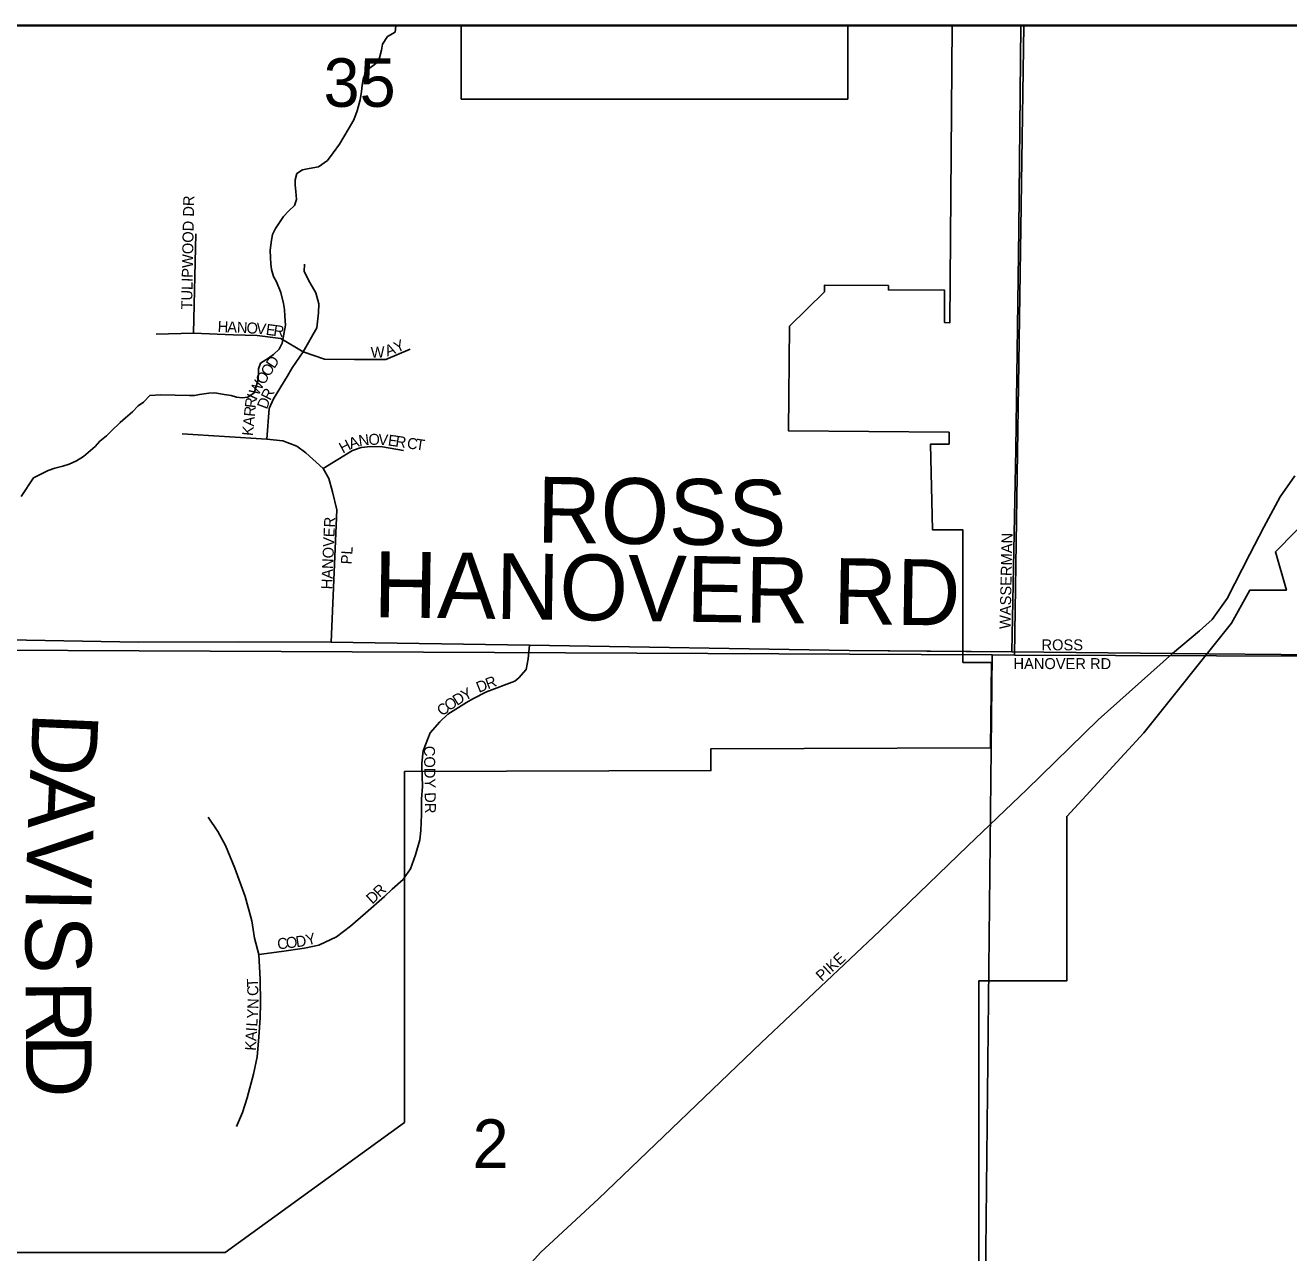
# Model space of a CAD drawing. Extents: x 0 to 34, y -2.3 to 22.
# Drawn here: x 6.815 to 7.907, y 19.84 to 20.9 of the extents above; entities that cross this region are included whole.
import ezdxf

# ---------------------------------------------------------------- set-up
doc = ezdxf.new("R2010")
doc.units = 0
for name, color, linetype in [('GM_X_City_Street', 7, 'Continuous'), ('GM_X_City_Street_Text', 7, 'Continuous'), ('GM_X_Corporation', 7, 'Continuous'), ('GM_X_County', 7, 'Continuous'), ('GM_X_County_Road', 7, 'Continuous'), ('GM_X_County_Road_Text', 7, 'Continuous'), ('GM_X_Minor_River', 7, 'Continuous'), ('GM_X_Section', 7, 'Continuous'), ('GM_X_Section_Text', 7, 'Continuous'), ('GM_X_Township', 7, 'Continuous'), ('GM_X_Township_Road_Text', 7, 'Continuous'), ('GM_X_Township_Subdivision', 7, 'Continuous'), ('GM_X_Township_Subdivision_Text', 7, 'Continuous'), ('SH_Data', 7, 'Continuous')]:
    doc.layers.add(name, color=color, linetype=linetype)

msp = doc.modelspace()

# ---------------------------------------------------------------- linework, layer by layer
at = {"layer": 'GM_X_City_Street'}
for p, q in [((7.6735, 20.7239), (7.6753, 20.8994)), ((7.6709, 20.5341), (7.6735, 20.7239)), ((7.6675, 20.359), (7.6709, 20.5341)), ((7.8992, 20.4928), (7.9119, 20.511)), ((7.885, 20.4666), (7.8992, 20.4928)), ((7.8729, 20.4434), (7.885, 20.4666)), ((7.8533, 20.4052), (7.8729, 20.4434)), ((7.8405, 20.387), (7.8533, 20.4052)), ((7.8296, 20.3771), (7.8405, 20.387)), ((7.8061, 20.3576), (7.8296, 20.3771)), ((7.6276, 20.3594), (7.6675, 20.359)), ((7.6675, 20.359), (7.8061, 20.3576)), ((7.7421, 20.3005), (7.8061, 20.3576)), ((7.8061, 20.3576), (7.8061, 20.3576)), ((7.6805, 20.2403), (7.7421, 20.3005)), ((7.1578, 20.2607), (7.158, 20.2631)), ((7.1585, 20.2428), (7.1578, 20.2607)), ((7.1575, 20.2318), (7.1585, 20.2428)), ((7.6295, 20.1916), (7.6805, 20.2403)), ((7.1576, 20.2187), (7.1575, 20.2318)), ((7.157, 20.2049), (7.1576, 20.2187)), ((7.1525, 20.1838), (7.1561, 20.1969)), ((7.1561, 20.1969), (7.157, 20.2049)), ((7.5535, 20.1183), (7.6295, 20.1916)), ((7.148, 20.1717), (7.1525, 20.1838)), ((7.1441, 20.166), (7.148, 20.1717)), ((7.4509, 20.0216), (7.5535, 20.1183)), ((7.3106, 19.887), (7.4509, 20.0216)), ((7.2603, 19.8406), (7.3106, 19.887)), ((7.2401, 19.8181), (7.2603, 19.8406))]:
    msp.add_line(p, q, dxfattribs=at)
at = {"layer": 'GM_X_Corporation'}
for p, q in [((7.5257, 20.8994), (7.1919, 20.8994)), ((7.1919, 20.8994), (7.192, 20.8362)), ((7.5257, 20.8362), (7.5257, 20.8994)), ((7.192, 20.8362), (7.5257, 20.8362))]:
    msp.add_line(p, q, dxfattribs=at)
for points in [[(7.6158, 20.8994), (7.6139, 20.6432), (7.6093, 20.6433), (7.6093, 20.6712), (7.5609, 20.6715), (7.5609, 20.6753), (7.5056, 20.6756), (7.5056, 20.6699), (7.4753, 20.6402), (7.4746, 20.5498), (7.6132, 20.5486), (7.6132, 20.5385), (7.5972, 20.5385), (7.5989, 20.4643), (7.6251, 20.4643), (7.6252, 20.35), (7.6499, 20.35), (7.649, 20.2763), (7.4075, 20.2755), (7.4075, 20.2566), (7.1428, 20.2557), (7.1428, 19.9527), (6.988, 19.8406), (6.6565, 19.8406)], [(8.8792, 19.7101), (8.8792, 20.8994), (7.6158, 20.8994)], [(6.7701, 19.2725), (6.8438, 19.2151), (6.8806, 19.2101), (7.0229, 19.2342), (7.1292, 19.2244), (7.1274, 19.3364), (7.6387, 19.3364), (7.6388, 20.075), (7.7148, 20.075), (7.7148, 20.217), (7.7814, 20.2892), (7.8572, 20.3839), (7.8729, 20.4123), (7.9045, 20.4123), (7.8951, 20.4454), (7.9466, 20.4977)]]:
    msp.add_lwpolyline(points, dxfattribs=at)
at = {"layer": 'GM_X_County'}
msp.add_line((8.8792, 20.8994), (2.0792, 20.8994), dxfattribs=at)
at = {"layer": 'GM_X_County_Road'}
for p, q in [((6.8005, 20.3694), (6.9133, 20.3674)), ((6.9133, 20.3674), (6.9998, 20.3678)), ((6.9998, 20.3678), (7.0796, 20.3674)), ((7.0796, 20.3674), (7.2509, 20.365)), ((7.2509, 20.365), (7.5268, 20.3604)), ((7.5268, 20.3604), (7.6276, 20.3594))]:
    msp.add_line(p, q, dxfattribs=at)
at = {"layer": 'GM_X_Minor_River'}
for p, q in [((7.1348, 20.894), (7.1355, 20.8994)), ((7.1239, 20.8836), (7.1282, 20.8904)), ((7.1282, 20.8904), (7.1348, 20.894)), ((7.1213, 20.872), (7.123, 20.8784)), ((7.123, 20.8784), (7.1239, 20.8836)), ((7.1093, 20.859), (7.1135, 20.8635)), ((7.1135, 20.8635), (7.1178, 20.8668)), ((7.1178, 20.8668), (7.1213, 20.872)), ((7.1063, 20.8481), (7.1072, 20.8534)), ((7.1072, 20.8534), (7.1093, 20.859)), ((7.1045, 20.8357), (7.1058, 20.8428)), ((7.1058, 20.8428), (7.1063, 20.8481)), ((7.102, 20.8262), (7.1045, 20.8357)), ((7.0992, 20.8184), (7.102, 20.8262)), ((7.0869, 20.7975), (7.0944, 20.8101)), ((7.0944, 20.8101), (7.0992, 20.8184)), ((7.0814, 20.79), (7.0869, 20.7975)), ((7.0763, 20.7833), (7.0814, 20.79)), ((7.0498, 20.7719), (7.0549, 20.7752)), ((7.0549, 20.7752), (7.0606, 20.7765)), ((7.0606, 20.7765), (7.0686, 20.7778)), ((7.0686, 20.7778), (7.0763, 20.7833)), ((7.0485, 20.7621), (7.0486, 20.7666)), ((7.0486, 20.7666), (7.0498, 20.7719)), ((7.0491, 20.7564), (7.0485, 20.7621)), ((7.0497, 20.7495), (7.0491, 20.7564)), ((7.043, 20.7399), (7.048, 20.7443)), ((7.048, 20.7443), (7.0497, 20.7495)), ((7.0316, 20.7246), (7.0383, 20.735)), ((7.0383, 20.735), (7.043, 20.7399)), ((7.0288, 20.7194), (7.0316, 20.7246)), ((7.027, 20.7058), (7.028, 20.7145)), ((7.028, 20.7145), (7.0288, 20.7194)), ((7.0272, 20.6993), (7.027, 20.7058)), ((7.0275, 20.694), (7.0272, 20.6993)), ((7.0281, 20.6891), (7.0275, 20.694)), ((7.0299, 20.683), (7.0281, 20.6891)), ((7.0324, 20.6784), (7.0299, 20.683)), ((7.036, 20.6692), (7.0324, 20.6784)), ((7.0384, 20.6597), (7.036, 20.6692)), ((7.0394, 20.6547), (7.0384, 20.6597)), ((7.0397, 20.649), (7.0394, 20.6547)), ((7.0402, 20.641), (7.0397, 20.649)), ((7.0372, 20.6256), (7.0402, 20.641)), ((7.0348, 20.6204), (7.0372, 20.6256)), ((7.0186, 20.6083), (7.0255, 20.6126)), ((7.0255, 20.6126), (7.0298, 20.6159)), ((7.0298, 20.6159), (7.0348, 20.6204)), ((7.0168, 20.5992), (7.0169, 20.6034)), ((7.0169, 20.6034), (7.0186, 20.6083)), ((7.013, 20.5826), (7.0163, 20.5928)), ((7.0163, 20.5928), (7.0168, 20.5992)), ((6.9176, 20.5745), (6.923, 20.5804)), ((6.923, 20.5804), (6.9325, 20.5809)), ((6.9325, 20.5809), (6.9572, 20.5803)), ((6.9572, 20.5803), (6.9617, 20.5805)), ((6.9617, 20.5805), (6.9659, 20.5812)), ((6.9659, 20.5812), (6.9739, 20.5825)), ((6.9739, 20.5825), (6.9792, 20.5827)), ((6.9792, 20.5827), (6.9872, 20.5814)), ((6.9872, 20.5814), (6.9932, 20.5805)), ((6.9932, 20.5805), (6.9978, 20.5789)), ((6.9978, 20.5789), (7.0027, 20.5784)), ((7.0027, 20.5784), (7.0076, 20.579)), ((7.0076, 20.579), (7.013, 20.5826)), ((6.9079, 20.5664), (6.9129, 20.5715)), ((6.9129, 20.5715), (6.9176, 20.5745)), ((6.89, 20.5498), (6.8974, 20.5572)), ((6.8974, 20.5572), (6.9021, 20.5612)), ((6.9021, 20.5612), (6.9079, 20.5664)), ((6.8857, 20.5457), (6.89, 20.5498)), ((6.8656, 20.5277), (6.8757, 20.5365)), ((6.8757, 20.5365), (6.8799, 20.5409)), ((6.8799, 20.5409), (6.8857, 20.5457)), ((6.8533, 20.5212), (6.8598, 20.524)), ((6.8598, 20.524), (6.8656, 20.5277)), ((6.8272, 20.5116), (6.8353, 20.5156)), ((6.8353, 20.5156), (6.841, 20.5177)), ((6.841, 20.5177), (6.8479, 20.5194)), ((6.8479, 20.5194), (6.8533, 20.5212)), ((6.812, 20.4931), (6.8226, 20.5094)), ((6.8226, 20.5094), (6.8272, 20.5116))]:
    msp.add_line(p, q, dxfattribs=at)
at = {"layer": 'GM_X_Section'}
for p, q in [((7.6777, 20.8994), (6.6703, 20.8994)), ((7.6696, 20.3563), (7.6777, 20.8994)), ((7.6777, 20.8994), (7.6696, 20.3563)), ((8.6806, 20.8994), (7.6777, 20.8994)), ((6.6643, 20.361), (7.6503, 20.3564)), ((6.6643, 20.361), (7.6503, 20.3564)), ((7.6503, 20.3564), (7.6398, 19.3493)), ((7.6398, 19.3493), (7.6503, 20.3564)), ((7.6503, 20.3564), (7.6696, 20.3563)), ((7.6503, 20.3564), (7.6696, 20.3563)), ((7.6696, 20.3563), (8.67, 20.3528)), ((7.6696, 20.3563), (8.67, 20.3528))]:
    msp.add_line(p, q, dxfattribs=at)
at = {"layer": 'GM_X_Township'}
for p, q in [((8.674, 20.8994), (2.6175, 20.8994)), ((6.8005, 20.3694), (6.9133, 20.3674)), ((6.8005, 20.3694), (6.9133, 20.3674)), ((6.9133, 20.3674), (6.9998, 20.3678)), ((6.9133, 20.3674), (6.9998, 20.3678)), ((6.9998, 20.3678), (7.0796, 20.3674)), ((6.9998, 20.3678), (7.0796, 20.3674)), ((7.0796, 20.3674), (7.2509, 20.365)), ((7.0796, 20.3674), (7.2509, 20.365)), ((7.2509, 20.365), (7.5268, 20.3604)), ((7.2509, 20.365), (7.5268, 20.3604)), ((7.5268, 20.3604), (7.6675, 20.359)), ((7.5268, 20.3604), (7.6675, 20.359)), ((7.6675, 20.359), (7.8061, 20.3576)), ((7.6675, 20.359), (7.8061, 20.3576)), ((7.8061, 20.3576), (8.2793, 20.353)), ((7.8061, 20.3576), (8.2793, 20.353))]:
    msp.add_line(p, q, dxfattribs=at)
at = {"layer": 'GM_X_Township_Subdivision'}
for p, q in [((6.9608, 20.6341), (6.9628, 20.7199)), ((7.0563, 20.6874), (7.0566, 20.6938)), ((7.0612, 20.678), (7.0563, 20.6874)), ((7.0664, 20.6691), (7.0612, 20.678)), ((7.0689, 20.6594), (7.0664, 20.6691)), ((7.0686, 20.6518), (7.0689, 20.6594)), ((7.0672, 20.6387), (7.0686, 20.6518)), ((6.9286, 20.6332), (6.9608, 20.6341)), ((6.9608, 20.6341), (6.9951, 20.6327)), ((7.0553, 20.6182), (7.0672, 20.6387)), ((6.9951, 20.6327), (7.0157, 20.6322)), ((7.0157, 20.6322), (7.036, 20.6296)), ((7.036, 20.6296), (7.0553, 20.6182)), ((7.0459, 20.6044), (7.0553, 20.6182)), ((7.0553, 20.6182), (7.0737, 20.6117)), ((7.0737, 20.6117), (7.0996, 20.6114)), ((7.0996, 20.6114), (7.1269, 20.6114)), ((7.1269, 20.6114), (7.1479, 20.6205)), ((7.0416, 20.5967), (7.0459, 20.6044)), ((7.0297, 20.5776), (7.0416, 20.5967)), ((7.0241, 20.5427), (7.0261, 20.5691)), ((7.0261, 20.5691), (7.0297, 20.5776)), ((7.0241, 20.5427), (6.9509, 20.5473)), ((7.0379, 20.5413), (7.0241, 20.5427)), ((7.0499, 20.5367), (7.0379, 20.5413)), ((7.0576, 20.531), (7.0499, 20.5367)), ((7.0979, 20.5328), (7.1056, 20.5355)), ((7.1056, 20.5355), (7.1138, 20.5365)), ((7.1138, 20.5365), (7.1238, 20.5362)), ((7.1238, 20.5362), (7.1421, 20.5328)), ((7.0727, 20.5174), (7.0576, 20.531)), ((7.0727, 20.5174), (7.0979, 20.5328)), ((7.0775, 20.5086), (7.0727, 20.5174)), ((7.0808, 20.4973), (7.0775, 20.5086)), ((7.0844, 20.4818), (7.0808, 20.4973)), ((7.0796, 20.3674), (7.0844, 20.4818)), ((7.2497, 20.3531), (7.2509, 20.365)), ((7.2479, 20.3439), (7.2497, 20.3531)), ((7.2416, 20.3366), (7.2479, 20.3439)), ((7.2138, 20.3245), (7.2383, 20.3339)), ((7.2383, 20.3339), (7.2416, 20.3366)), ((7.1965, 20.3153), (7.202, 20.3186)), ((7.202, 20.3186), (7.2138, 20.3245)), ((7.1804, 20.3052), (7.1965, 20.3153)), ((7.1652, 20.2891), (7.1735, 20.2986)), ((7.1735, 20.2986), (7.1804, 20.3052)), ((7.159, 20.2735), (7.1652, 20.2891)), ((7.158, 20.2631), (7.159, 20.2735)), ((6.9817, 20.2041), (6.9734, 20.2165)), ((6.9882, 20.1919), (6.9817, 20.2041)), ((6.9965, 20.1724), (6.9882, 20.1919)), ((7.0053, 20.148), (6.9965, 20.1724)), ((7.1418, 20.1626), (7.1441, 20.166)), ((7.1256, 20.148), (7.1322, 20.1543)), ((7.1322, 20.1543), (7.1418, 20.1626)), ((7.0111, 20.127), (7.0053, 20.148)), ((7.1091, 20.1335), (7.1256, 20.148)), ((7.0962, 20.1223), (7.1091, 20.1335)), ((7.0135, 20.112), (7.0111, 20.127)), ((7.0841, 20.1132), (7.0962, 20.1223)), ((7.017, 20.0977), (7.0135, 20.112)), ((7.069, 20.1059), (7.0841, 20.1132)), ((7.017, 20.0977), (7.0366, 20.1004)), ((7.0366, 20.1004), (7.0566, 20.1032)), ((7.0566, 20.1032), (7.069, 20.1059)), ((7.0182, 20.0762), (7.017, 20.0977)), ((7.0185, 20.0562), (7.0182, 20.0762)), ((7.0182, 20.0431), (7.0185, 20.0562)), ((7.017, 20.0266), (7.0182, 20.0431)), ((7.0156, 20.0095), (7.017, 20.0266)), ((7.0124, 19.9946), (7.0156, 20.0095)), ((7.007, 19.9741), (7.0124, 19.9946)), ((7.0029, 19.9613), (7.007, 19.9741)), ((6.9977, 19.9493), (7.0029, 19.9613))]:
    msp.add_line(p, q, dxfattribs=at)
at = {"layer": 'SH_Data'}
msp.add_line((2.1, 20.9), (8.9, 20.9), dxfattribs=at)

# ---------------------------------------------------------------- texts
at = {"layer": 'GM_X_City_Street_Text'}
for s, rotation, p in [('WASSERMAN', 88.7128, (7.6662, 20.3787)), ('ROSS', 0, (7.693, 20.3604)), ('HANOVER RD', 0, (7.6688, 20.3442)), ('CODY DR', 270.9235, (7.1597, 20.2779)), ('PIKE', 42.3976, (7.5034, 20.0741))]:
    msp.add_text(s, height=0.00947, rotation=rotation, dxfattribs=at).set_placement(p)
at = {"layer": 'GM_X_County_Road_Text'}
for s, rotation, p in [('ROSS', 359.1731, (7.2571, 20.4535)), ('HANOVER RD', 359.1584, (7.116, 20.3891))]:
    msp.add_text(s, height=0.05682, rotation=rotation, dxfattribs=at).set_placement(p)
at = {"layer": 'GM_X_Section_Text'}
for s, height, p in [('35', 0.04186, (7.073, 20.8296)), ('2', 0.0419, (7.2017, 19.9136))]:
    msp.add_text(s, height=height, rotation=0, dxfattribs=at).set_placement(p)
at = {"layer": 'GM_X_Township_Road_Text'}
for s, rotation, p in [('D', 267.524, (6.822, 20.3077)), ('A', 267.5282, (6.8198, 20.2577)), ('V', 268.1229, (6.8176, 20.2071)), ('I', 269.1067, (6.816, 20.1561)), ('S', 270.0325, (6.8156, 20.1318)), ('R', 270.2683, (6.8157, 20.0757)), ('D', 270.2693, (6.8159, 20.029))]:
    msp.add_text(s, height=0.0568, rotation=rotation, dxfattribs=at).set_placement(p)
at = {"layer": 'GM_X_Township_Subdivision_Text'}
for s, rotation, p in [('TULIPWOOD DR', 88.9083, (6.9595, 20.6545)), ('H', 357.1793, (6.9814, 20.6354)), ('A', 357.1781, (6.9897, 20.635)), ('N', 357.1793, (6.998, 20.6346)), ('O', 356.8071, (7.0063, 20.6342)), ('V', 354.11, (7.0145, 20.6338)), ('E', 352.6301, (7.0228, 20.6329)), ('R', 351.5419, (7.0293, 20.6321)), ('W', 1.8834, (7.1139, 20.6129)), ('A', 20.8904, (7.1281, 20.614)), ('Y', 23.8208, (7.1363, 20.6171)), ('D', 57.0888, (7.0305, 20.603)), ('O', 57.0934, (7.0215, 20.589)), ('O', 57.0934, (7.026, 20.596)), ('W', 62.8071, (7.0166, 20.5796)), ('I', 65.4592, (7.0149, 20.5759)), ('R', 62.9245, (7.0269, 20.5755)), ('R', 84.5528, (7.0136, 20.5618)), ('R', 83.4473, (7.0143, 20.5692)), ('D', 69.5104, (7.0241, 20.568)), ('A', 84.5558, (7.0128, 20.5535)), ('K', 84.5558, (7.012, 20.5452)), ('N', 7.7831, (7.1039, 20.5366)), ('O', 1.2241, (7.1119, 20.5377)), ('V', 355.471, (7.12, 20.5379)), ('E', 352.2717, (7.1282, 20.5373)), ('H', 28.0802, (7.0896, 20.5302)), ('A', 19.3594, (7.0966, 20.534)), ('R', 351.6896, (7.1347, 20.5364)), ('C', 351.6896, (7.1446, 20.5349)), ('T', 351.7013, (7.1521, 20.5338)), ('HANOVER', 87.4737, (7.0804, 20.4129)), ('PL', 86.4254, (7.0973, 20.4344)), ('Y', 29.2027, (7.1951, 20.3166)), ('D', 22.1302, (7.2072, 20.3236)), ('R', 20.3628, (7.2149, 20.3267)), ('O', 33.2536, (7.1812, 20.3077)), ('D', 32.0228, (7.1882, 20.3123)), ('C', 39.9058, (7.1757, 20.3031)), ('R', 43.485, (7.1214, 20.1466)), ('D', 42.4567, (7.1151, 20.1408)), ('C', 6.7425, (7.0336, 20.1021)), ('O', 6.7367, (7.0411, 20.103)), ('D', 8.6192, (7.0497, 20.104)), ('Y', 15.0768, (7.0591, 20.1055)), ('T', 92.2058, (7.0165, 20.0697)), ('C', 92.1103, (7.0168, 20.0622)), ('N', 88.6135, (7.0167, 20.0507)), ('Y', 86.5995, (7.0162, 20.0421)), ('I', 86.5995, (7.0155, 20.0312)), ('L', 86.5977, (7.0158, 20.0354)), ('K', 86.5995, (7.0145, 20.0146)), ('A', 86.6009, (7.015, 20.0229))]:
    msp.add_text(s, height=0.00947, rotation=rotation, dxfattribs=at).set_placement(p)

doc.saveas('drawing.dxf')
